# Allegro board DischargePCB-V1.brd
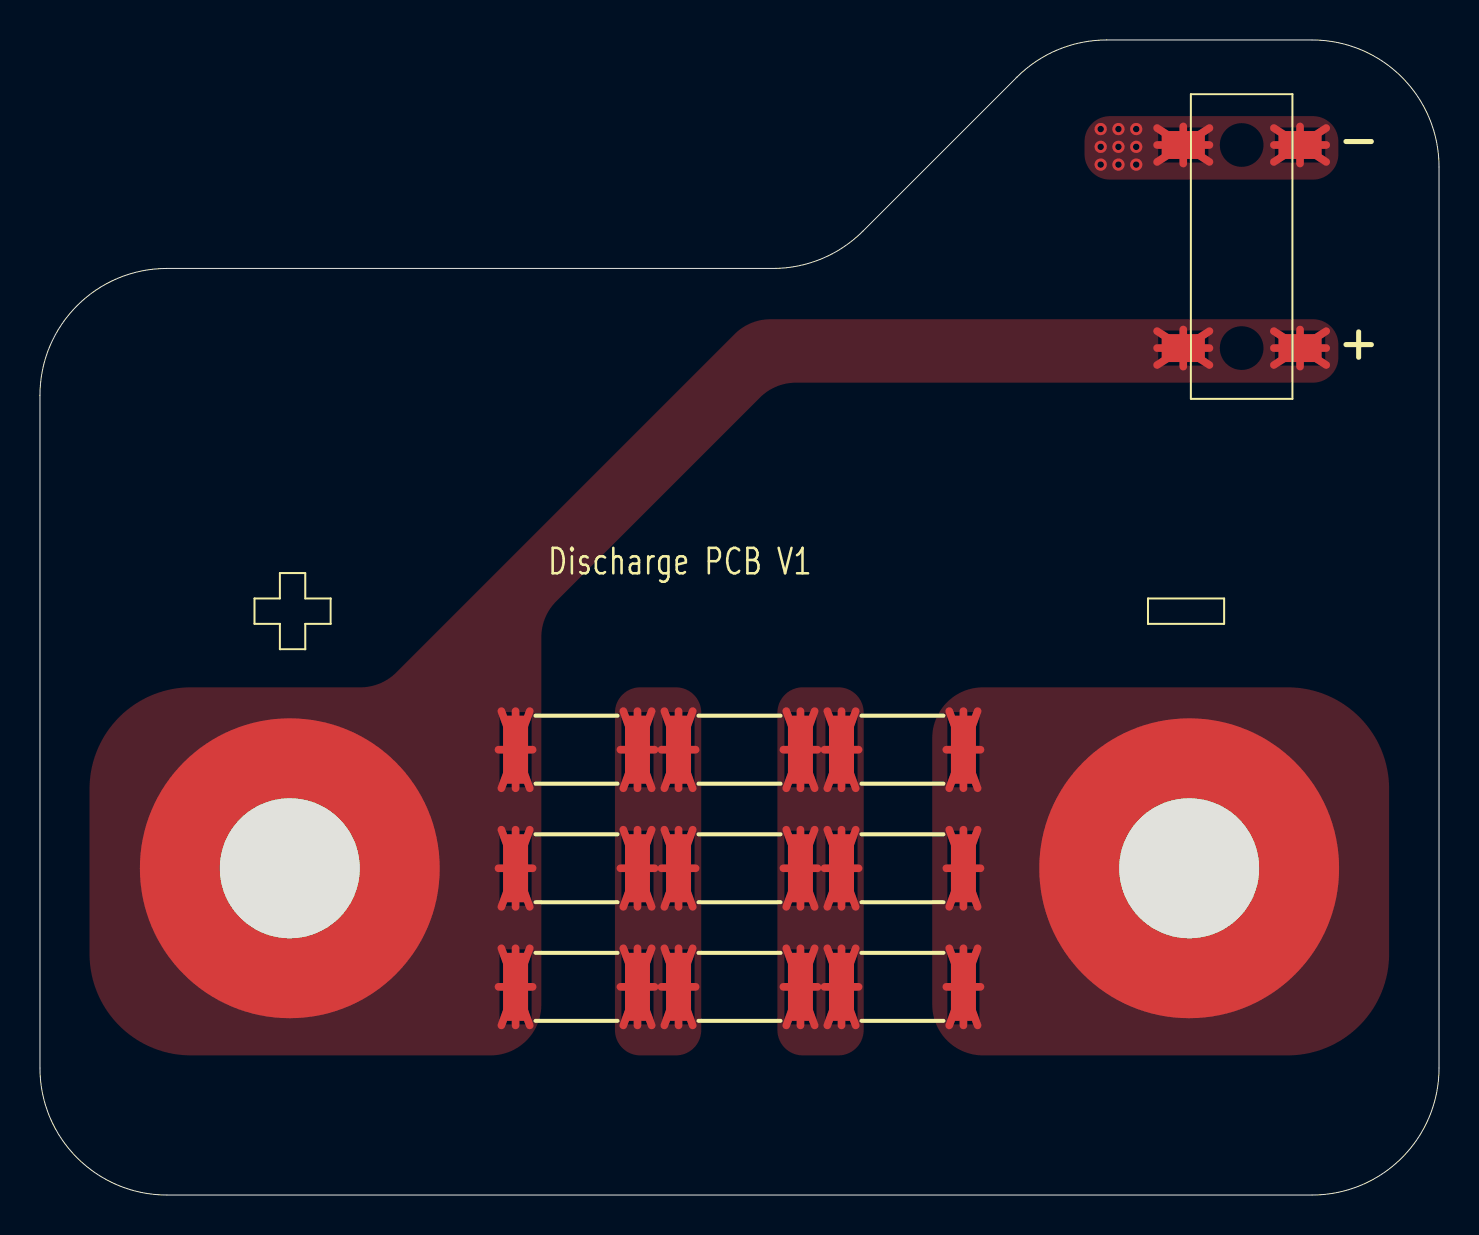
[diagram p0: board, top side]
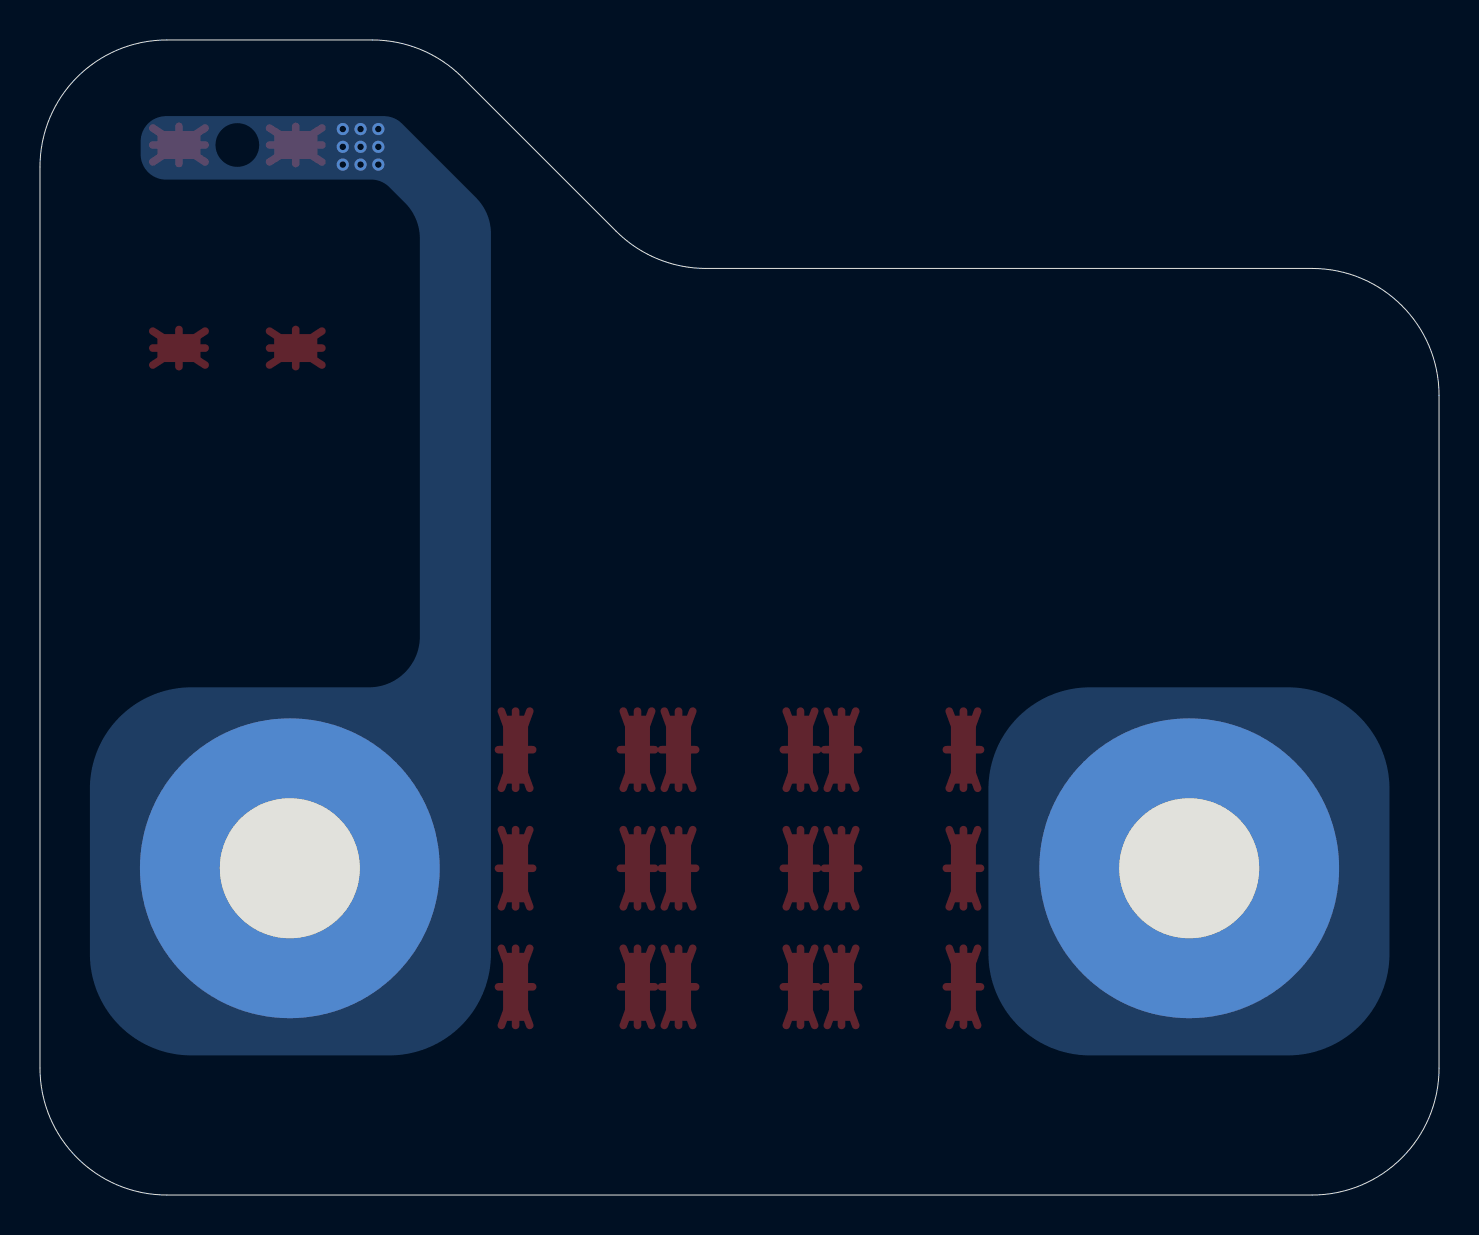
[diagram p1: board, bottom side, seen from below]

Outline 70 x 57.78 mm; copper layers: TOP, BOTTOM. Coordinates in mm from the lower left corner of the outline.
Outline path: 0,40 arc(1.86,44.5) 6.35,46.36 36.68,46.36 arc(39.11,46.84) 41.17,48.21 48.88,55.93 arc(50.94,57.3) 53.37,57.78 63.65,57.78 arc(68.14,55.93) 70,51.44 70,6.35 arc(68.14,1.86) 63.65,0 6.35,0 arc(1.86,1.86) 0,6.35 0,40

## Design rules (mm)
constraint set DEFAULT: min track width 0.178
net group MID: nets N234316 N234320

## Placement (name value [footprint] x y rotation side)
C1  300uF  [CAPFCOAX_FT]  35 16.35 135 top
J1  CON2_400mil_SM  [2POS_400MIL_SM]  60.12 47.45 180 top
NOREF  -  []  55.89 0 90 top
NOREF#2  -  []  0 24.76 0 top
R1  100k  [RESC6432X70N]  26.85 10.42 0 top
R2  100k  [RESC6432X70N]  35 10.42 0 top
R3  100k  [RESC6432X70N]  43.15 10.42 0 top
R4  100k  [RESC6432X70N]  26.85 16.35 0 top
R5  100k  [RESC6432X70N]  35 16.35 0 top
R6  100k  [RESC6432X70N]  43.15 16.35 0 top
R7  100k  [RESC6432X70N]  26.85 22.28 0 top
R8  100k  [RESC6432X70N]  35 22.28 0 top
R9  100k  [RESC6432X70N]  43.15 22.28 0 top

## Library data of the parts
C1 = CAP NP
J1 = CON2_400mil_SM
R1-R9 = R

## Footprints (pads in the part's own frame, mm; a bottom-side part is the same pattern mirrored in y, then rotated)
2POS_400MIL_SM
  round 0 hole 1.778 unplated: (0,5.08) (0,0) (0,-5.08)
  rect 2.159x1.397 smd: 1(-2.921,5.08) 2(-2.921,-5.08) 3(2.921,5.08) 4(2.921,-5.08)
CAPFCOAX_FT
  round 15 hole 7: 1(15.91,15.91) 2(-15.91,-15.91)
RESC6432X70N
  rect 1.25x3.4 smd: 1(-3.05,0) 2(3.05,0)

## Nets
DC+: C1.1 J1.1 J1.3 R1.1 R4.1 R7.1
DC-: C1.2 J1.2 J1.4 R3.2 R6.2 R9.2
N234316: R1.2 R2.1 R4.2 R5.1 R7.2 R8.1
N234320: R2.2 R3.1 R5.2 R6.1 R8.2 R9.1

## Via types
v1: diameter 0.61, hole 0.33, TOP to BOTTOM, 9 vias

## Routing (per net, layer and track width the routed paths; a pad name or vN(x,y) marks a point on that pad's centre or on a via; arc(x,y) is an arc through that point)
DC+: length 62.8
  TOP w0.381: 55.9,42.37 J1.3 ; J1.3 58.51,43.22 ; J1.3 57.2,43.3 ; J1.3 55.9,43.22 ; J1.3 58.51,42.37 ; J1.3 55.9,41.52 ; J1.3 58.51,41.52 ; J1.3 57.2,41.44 ; R1.1 24.65,10.42 ; R1.1 23.8,8.49 ; R1.1 23.8,12.34 ; R1.1 23.09,12.34 ; R1.1 23.09,8.49 ; R1.1 22.94,10.42 ; R1.1 24.51,8.49 ; R1.1 24.51,12.34 ; 61.74,42.37 J1.1 ; J1.1 63.05,41.44 ; J1.1 64.35,42.37 ; J1.1 64.35,43.22 ; J1.1 64.35,41.52 ; J1.1 61.74,43.22 ; J1.1 61.74,41.52 ; J1.1 63.05,43.3 ; 23.09,24.21 R7.1 ; R7.1 23.8,20.35 ; R7.1 24.65,22.28 ; R7.1 23.09,20.35 ; R7.1 22.94,22.28 ; R7.1 24.51,24.21 ; R7.1 24.51,20.35 ; R7.1 23.8,24.21 ; 22.94,16.35 R4.1 ; R4.1 23.09,14.42 ; R4.1 24.51,14.42 ; R4.1 24.65,16.35 ; R4.1 23.8,14.42 ; R4.1 24.51,18.28 ; R4.1 23.09,18.28 ; R4.1 23.8,18.28
DC-: length 62.8
  TOP w0.381: J1.4 58.51,52.53 ; J1.4 55.9,52.53 ; J1.4 58.51,51.68 ; J1.4 57.2,53.46 ; J1.4 55.9,51.68 ; J1.4 57.2,51.6 ; J1.4 55.9,53.38 ; J1.4 58.51,53.38 ; R6.2 47.06,16.35 ; R6.2 45.35,16.35 ; R6.2 46.91,14.42 ; R6.2 46.91,18.28 ; R6.2 45.49,18.28 ; R6.2 46.2,18.28 ; R6.2 45.49,14.42 ; R6.2 46.2,14.42 ; 61.74,52.53 J1.2 ; J1.2 61.74,51.68 ; J1.2 64.35,53.38 ; J1.2 63.05,53.46 ; J1.2 63.05,51.6 ; J1.2 61.74,53.38 ; J1.2 64.35,51.68 ; J1.2 64.35,52.53 ; R3.2 47.06,10.42 ; R3.2 46.2,12.34 ; R3.2 46.91,8.49 ; R3.2 46.91,12.34 ; R3.2 46.2,8.49 ; R3.2 45.35,10.42 ; R3.2 45.49,12.34 ; R3.2 45.49,8.49 ; 45.35,22.28 R9.2 ; R9.2 46.2,20.35 ; R9.2 45.49,20.35 ; R9.2 46.91,24.21 ; R9.2 47.06,22.28 ; R9.2 45.49,24.21 ; R9.2 46.2,24.21 ; R9.2 46.91,20.35
  vias: v1(53.07,53.33) v1(53.07,52.44) v1(53.07,51.55) v1(53.96,53.33) v1(53.96,52.44) v1(53.96,51.55) v1(54.85,53.33) v1(54.85,52.44) v1(54.85,51.55)
N234316: length 82.7
  TOP w0.381: 29.19,24.21 R7.2 ; R7.2 30.75,22.28 ; R7.2 29.9,20.35 ; R7.2 29.19,20.35 ; R7.2 29.04,22.28 ; R7.2 29.9,24.21 ; R7.2 30.61,24.21 ; R7.2 30.61,20.35 ; R4.2 30.75,16.35 ; R4.2 29.19,18.28 ; R4.2 30.61,18.28 ; R4.2 29.19,14.42 ; R4.2 29.9,18.28 ; R4.2 30.61,14.42 ; R4.2 29.04,16.35 ; R4.2 29.9,14.42 ; 31.95,14.42 R5.1 ; R5.1 31.24,14.42 ; R5.1 31.24,18.28 ; R5.1 32.66,18.28 ; R5.1 31.1,16.35 ; R5.1 32.8,16.35 ; R5.1 31.95,18.28 ; R5.1 32.66,14.42 ; 29.9,8.49 R1.2 ; R1.2 29.19,12.34 ; R1.2 30.61,8.49 ; R1.2 30.75,10.42 ; R1.2 29.19,8.49 ; R1.2 29.9,12.34 ; R1.2 29.04,10.42 ; R1.2 30.61,12.34 ; R2.1 32.8,10.42 ; R2.1 31.95,8.49 ; R2.1 32.66,8.49 ; R2.1 31.1,10.42 ; R2.1 32.66,12.34 ; R2.1 31.24,12.34 ; R2.1 31.24,8.49 ; R2.1 31.95,12.34 ; R8.1 32.8,22.28 ; R8.1 31.95,20.35 ; R8.1 32.66,24.21 ; R8.1 32.66,20.35 ; R8.1 31.1,22.28 ; R8.1 31.24,24.21 ; R8.1 31.24,20.35 ; R8.1 31.95,24.21
N234320: length 82.7
  TOP w0.381: 37.2,10.42 R2.2 ; R2.2 38.9,10.42 ; R2.2 38.76,12.34 ; R2.2 38.76,8.49 ; R2.2 37.34,8.49 ; R2.2 38.05,12.34 ; R2.2 38.05,8.49 ; R2.2 37.34,12.34 ; 39.25,10.42 R3.1 ; R3.1 40.1,12.34 ; R3.1 39.39,12.34 ; R3.1 40.1,8.49 ; R3.1 40.96,10.42 ; R3.1 39.39,8.49 ; R3.1 40.81,12.34 ; R3.1 40.81,8.49 ; 37.2,16.35 R5.2 ; R5.2 38.76,14.42 ; R5.2 37.34,18.28 ; R5.2 37.34,14.42 ; R5.2 38.76,18.28 ; R5.2 38.05,14.42 ; R5.2 38.05,18.28 ; R5.2 38.9,16.35 ; R9.1 40.1,24.21 ; R9.1 39.39,24.21 ; R9.1 40.96,22.28 ; R9.1 40.1,20.35 ; R9.1 40.81,20.35 ; R9.1 39.39,20.35 ; R9.1 40.81,24.21 ; R9.1 39.25,22.28 ; 39.39,14.42 R6.1 ; R6.1 40.81,18.28 ; R6.1 40.1,14.42 ; R6.1 40.1,18.28 ; R6.1 39.25,16.35 ; R6.1 40.96,16.35 ; R6.1 39.39,18.28 ; R6.1 40.81,14.42 ; 37.34,20.35 R8.2 ; R8.2 38.05,20.35 ; R8.2 38.9,22.28 ; R8.2 37.2,22.28 ; R8.2 38.76,24.21 ; R8.2 38.76,20.35 ; R8.2 37.34,24.21 ; R8.2 38.05,24.21

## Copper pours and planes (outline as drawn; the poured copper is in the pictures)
DC+ on TOP: 7.56,6.98 3.97,8.47 2.48,12.07 2.48,20.32 3.97,23.91 7.56,25.4 16.03,25.4 17,25.59 17.83,26.14 34.76,43.07 35.58,43.62 36.55,43.81 63.69,43.81 64.59,43.44 64.96,42.55 64.96,41.91 64.59,41.01 63.69,40.64 37.82,40.64 36.85,40.45 36.03,39.9 25.83,29.7 25.28,28.88 25.09,27.9 25.09,9.53 24.34,7.73 22.55,6.98
DC+ on BOTTOM: 2.48,12.07 3.97,8.47 7.56,6.98 17.47,6.98 21.06,8.47 22.55,12.07 22.55,20.32 21.06,23.91 17.47,25.4 7.56,25.4 3.97,23.91 2.48,20.32
DC- on TOP: 63.69,50.8 64.59,51.17 64.96,52.07 64.96,52.71 64.59,53.6 63.69,53.97 53.53,53.97 52.64,53.6 52.26,52.71 52.26,52.07 52.64,51.17 53.53,50.8
DC- on TOP: 47.18,6.98 45.39,7.73 44.64,9.53 44.64,22.86 45.39,24.66 47.18,25.4 62.42,25.4 66.02,23.91 67.5,20.32 67.5,12.07 66.02,8.47 62.42,6.98
DC- on BOTTOM: 64.96,52.71 64.59,53.6 63.69,53.97 52.79,53.97 52.3,53.88 51.89,53.6 48.18,49.89 47.63,49.07 47.44,48.1 47.44,12.07 48.93,8.47 52.52,6.98 62.42,6.98 66.02,8.47 67.5,12.07 67.5,20.32 66.02,23.91 62.42,25.4 53.53,25.4 51.74,26.14 50.99,27.94 50.99,47.84 51.19,48.81 51.74,49.64 52.53,50.43 52.94,50.7 53.42,50.8 63.69,50.8 64.59,51.17 64.96,52.07
N234316 on TOP: 30.04,25.4 29.14,25.03 28.77,24.13 28.77,8.26 29.14,7.36 30.04,6.98 31.82,6.98 32.71,7.36 33.09,8.26 33.09,24.13 32.71,25.03 31.82,25.4
N234320 on TOP: 38.17,25.4 37.27,25.03 36.9,24.13 36.9,8.26 37.27,7.36 38.17,6.98 39.94,6.98 40.84,7.36 41.21,8.26 41.21,24.13 40.84,25.03 39.94,25.4

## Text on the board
Ref Des/Silkscreen Top: Discharge PCB V1
NCLEGEND-1-2: FIGURE | FINISHED_SIZE | 13.0 | 275.59 | 70.0 | DRILL CHART: TOP to BOTTOM | ALL UNITS ARE IN MILS | PLATED | NON-PLATED | QTY | 9 | 2 | 3
XSECTION_CHART: *  SURFACE | L1 TOP CONDUCTOR | *  DIELECTRIC | L2 BOTTOM CONDUCTOR | DESIGN CROSS SECTION CHART | ___________________________ | TOTAL THICKNESS 62 MIL | 1-2
